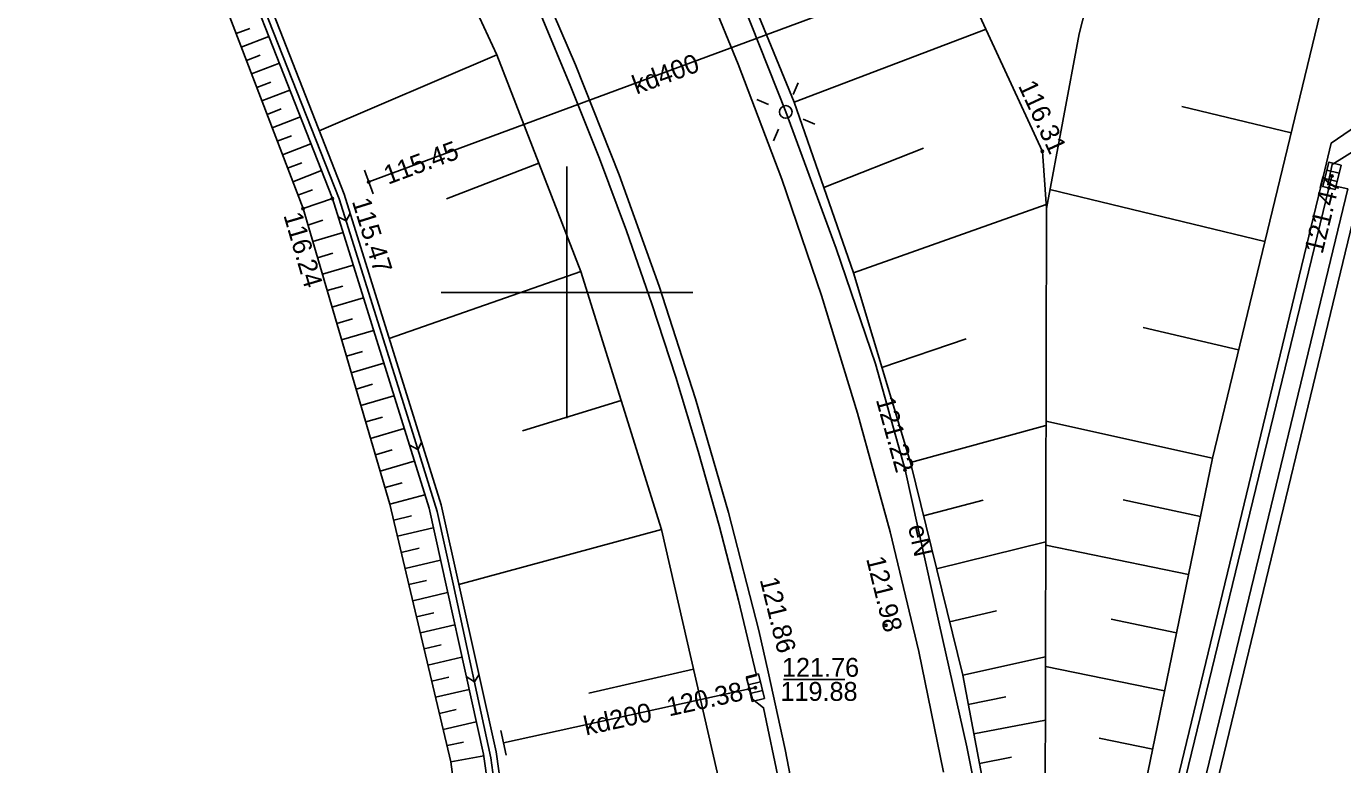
# Model space of a CAD drawing. Extents: x 6424617 to 6425697, y 5665845 to 5667190.
# Drawn here: x 6425378.5 to 6425430.8, y 5666881.2 to 5666910.6 of the extents above; entities that cross this region are included whole.
import ezdxf

# ---------------------------------------------------------------- set-up
doc = ezdxf.new("R2010")
doc.units = 0
for name, color, linetype in [('Warstwa 12', 7, 'Continuous'), ('Warstwa 13', 7, 'Continuous'), ('Warstwa 14', 7, 'Continuous'), ('Warstwa 15', 7, 'Continuous'), ('Warstwa 2', 7, 'Continuous'), ('Warstwa 20', 7, 'Continuous'), ('Warstwa 21', 7, 'Continuous'), ('Warstwa 25', 7, 'Continuous'), ('Warstwa 4', 7, 'Continuous'), ('Warstwa 47', 7, 'Continuous'), ('Warstwa 6', 7, 'Continuous'), ('Warstwa 63', 7, 'Continuous'), ('Warstwa 8', 7, 'Continuous'), ('Warstwa 9', 7, 'Continuous')]:
    doc.layers.add(name, color=color, linetype=linetype)

msp = doc.modelspace()

# ---------------------------------------------------------------- linework, layer by layer
at = {"layer": 'Warstwa 12'}
for points in [[(6425348.14, 5666997.42), (6425353.37, 5666990.86), (6425362.83, 5666978.49), (6425371.96, 5666966.45), (6425386.81, 5666946.74), (6425392.86, 5666938.27), (6425396.85, 5666931.85), (6425399.93, 5666926.36), (6425402.86, 5666920.8), (6425405.92, 5666914.19), (6425408.7, 5666907.17), (6425410.7, 5666901.75), (6425412.27, 5666897.16), (6425413.44, 5666892.95), (6425414.78, 5666886.9), (6425415.89, 5666881.95), (6425416.77, 5666877.58), (6425417.4, 5666873.25), (6425418.12, 5666868.16), (6425418.38, 5666863.9), (6425418.7, 5666858.55), (6425418.2, 5666857.76)], [(6425418.31, 5666914.08), (6425392.12, 5666904.39)], [(6425418.2, 5666857.76), (6425418.82, 5666858.12), (6425430.06, 5666904.59), (6425430.38, 5666905.93), (6425431.89, 5666906.96)], [(6425430.41, 5666904.63), (6425423.78, 5666877.4), (6425418.69, 5666856.25), (6425418.65, 5666856.01)], [(6425397.48, 5666882.11), (6425407.49, 5666884.3)]]:
    msp.add_lwpolyline(points, dxfattribs=at)
at = {"layer": 'Warstwa 14'}
msp.add_line((6425411.043, 5666884.619), (6425408.603, 5666884.619), dxfattribs=at)
for centre in [(6425392.12, 5666904.39), (6425430.41, 5666904.63), (6425430.292, 5666904.144), (6425413.44, 5666892.95), (6425407.49, 5666884.3), (6425407.246, 5666884.247)]:
    msp.add_circle(centre, 0.045, dxfattribs=at)
at = {"layer": 'Warstwa 2'}
msp.add_circle((6425408.7, 5666907.17), 0.25, dxfattribs=at)
at = {"layer": 'Warstwa 20'}
for points in [[(6425314.103, 5667029.211), (6425315.581, 5667026.396), (6425321.09, 5667017.329), (6425326.707, 5667009.007), (6425332.328, 5667001.644), (6425369.012, 5666954.157), (6425382.127, 5666936.484), (6425388.892, 5666925.984), (6425393.247, 5666917.98), (6425397.216, 5666909.432), (6425400.558, 5666900.834), (6425403.756, 5666890.579), (6425406.309, 5666879.499), (6425407.78, 5666870.067), (6425408.67, 5666859.825), (6425408.853, 5666850.565), (6425408.345, 5666840.039), (6425407.685, 5666833.993), (6425407.004, 5666828.248), (6425405.898, 5666821.141), (6425404.522, 5666813.522)], [(6425393.298, 5666813.657), (6425395.438, 5666825.508), (6425396.774, 5666840.178), (6425397.83, 5666855.444), (6425397.308, 5666867.017), (6425395.387, 5666881.357), (6425392.961, 5666891.594), (6425389.511, 5666903.33), (6425384.19, 5666917.231), (6425380.005, 5666924.769), (6425372.43, 5666937.379), (6425363.259, 5666950.219), (6425359.316, 5666956.212), (6425352.524, 5666966.198), (6425341.504, 5666981.912), (6425329.825, 5666997.688), (6425317.161, 5667014.853), (6425313.991, 5667019.921)], [(6425349.632, 5666996.03), (6425376.62, 5666961.102), (6425380.441, 5666956.131), (6425386.586, 5666947.957), (6425392.505, 5666939.498), (6425397.085, 5666932.217), (6425401.495, 5666924.286), (6425406.312, 5666914.18), (6425409.035, 5666907.556), (6425411.392, 5666900.784), (6425413.657, 5666893.241), (6425415.732, 5666884.803), (6425417.068, 5666877.78), (6425418.262, 5666868.956), (6425418.975, 5666860.884)], [(6425418.975, 5666860.884), (6425420.91, 5666870.31), (6425425.66, 5666893.41), (6425431.91, 5666919.26)]]:
    msp.add_lwpolyline(points, dxfattribs=at)
at = {"layer": 'Warstwa 21'}
for p, q in [((6425392.292, 5666903.921), (6425391.948, 5666904.859)), ((6425397.588, 5666881.622), (6425397.372, 5666882.598))]:
    msp.add_line(p, q, dxfattribs=at)
for points in [[(6425314.038, 5667023.847), (6425318.834, 5667016.073), (6425331.461, 5666998.529), (6425342.663, 5666983.502), (6425354.15, 5666967.599), (6425365.232, 5666951.474), (6425373.98, 5666938.422), (6425381.71, 5666925.538), (6425385.644, 5666917.945), (6425391.142, 5666903.901), (6425395.001, 5666891.557), (6425397.184, 5666881.754), (6425399.285, 5666866.812), (6425399.444, 5666855.685), (6425398.462, 5666840.068), (6425397.038, 5666824.899), (6425394.925, 5666813.637)], [(6425314.027, 5667022.896), (6425318.409, 5667015.8), (6425331.056, 5666998.236), (6425342.258, 5666983.209), (6425353.745, 5666967.307), (6425364.827, 5666951.201), (6425373.555, 5666938.149), (6425381.265, 5666925.286), (6425385.18, 5666917.733), (6425390.679, 5666903.729), (6425394.518, 5666891.426), (6425396.682, 5666881.663), (6425398.785, 5666866.781), (6425398.944, 5666855.694), (6425397.963, 5666840.107), (6425396.539, 5666824.968), (6425394.409, 5666813.644)], [(6425418.975, 5666860.884), (6425419.06, 5666903.33), (6425418.902, 5666905.6), (6425415.908, 5666912.076), (6425410.886, 5666921.5), (6425406.057, 5666930.53), (6425401.387, 5666938.317), (6425394.923, 5666946.546), (6425388.818, 5666954.159), (6425381.634, 5666961.791), (6425371.584, 5666973.036), (6425362.387, 5666983.346), (6425359.931, 5666986.941), (6425351.65, 5666994.223), (6425349.632, 5666996.03)], [(6425418.975, 5666860.884), (6425419.06, 5666903.33), (6425420.356, 5666910.275), (6425421.335, 5666914.059)]]:
    msp.add_lwpolyline(points, dxfattribs=at)
at = {"layer": 'Warstwa 25'}
for centre in [(6425418.902, 5666905.6), (6425390.679, 5666903.729), (6425389.511, 5666903.33), (6425412.68, 5666886.776), (6425408.792, 5666885.876)]:
    msp.add_circle(centre, 0.045, dxfattribs=at)
at = {"layer": 'Warstwa 4'}
for p, q in [((6425430.695, 5666904.74), (6425430.209, 5666904.86)), ((6425430.611, 5666904.4), (6425430.125, 5666904.52)), ((6425407.693, 5666884.528), (6425407.207, 5666884.413)), ((6425407.773, 5666884.187), (6425407.287, 5666884.072))]:
    msp.add_line(p, q, dxfattribs=at)
for points in [[(6425408.993, 5666907.86), (6425409.188, 5666908.321)], [(6425408.01, 5666907.463), (6425407.549, 5666907.658)], [(6425409.39, 5666906.877), (6425409.851, 5666906.682)], [(6425408.407, 5666906.48), (6425408.212, 5666906.019)]]:
    msp.add_lwpolyline(points, dxfattribs=at)
for points in [[(6425430.773, 5666905.055), (6425430.533, 5666904.085), (6425430.047, 5666904.205), (6425430.287, 5666905.175)], [(6425407.619, 5666884.844), (6425407.848, 5666883.871), (6425407.361, 5666883.756), (6425407.132, 5666884.729)]]:
    msp.add_lwpolyline(points, close=True, dxfattribs=at)
at = {"layer": 'Warstwa 47'}
for points in [[(6425314.103, 5667029.211), (6425315.581, 5667026.396), (6425321.09, 5667017.329), (6425326.707, 5667009.007), (6425332.328, 5667001.644), (6425369.012, 5666954.157), (6425382.127, 5666936.484), (6425388.892, 5666925.984), (6425393.247, 5666917.98), (6425397.216, 5666909.432), (6425400.558, 5666900.834), (6425403.756, 5666890.579), (6425406.309, 5666879.499), (6425407.78, 5666870.067), (6425408.67, 5666859.825), (6425408.853, 5666850.565), (6425408.345, 5666840.039), (6425407.685, 5666833.993), (6425407.004, 5666828.248), (6425405.898, 5666821.141), (6425404.522, 5666813.522)], [(6425434.482, 5666938.566), (6425431.91, 5666919.26), (6425425.66, 5666893.41), (6425420.91, 5666870.31), (6425418.975, 5666860.884)]]:
    msp.add_lwpolyline(points, dxfattribs=at)
at = {"layer": 'Warstwa 6'}
for points in [[(6425436.9, 5666928.04), (6425436.812, 5666928.004), (6425436.564, 5666927.008), (6425436.159, 5666926.755), (6425435.965, 5666925.969), (6425436.293, 5666925.883), (6425431.397, 5666905.695), (6425430.416, 5666905.082), (6425430.241, 5666904.285), (6425431.039, 5666904.111), (6425424.834, 5666878.494), (6425423.823, 5666877.862), (6425423.658, 5666877.065), (6425424.455, 5666876.9), (6425419.634, 5666856.991), (6425418.663, 5666856.398), (6425418.469, 5666855.612), (6425419.071, 5666854.62), (6425418.186, 5666851.005), (6425418.674, 5666850.886)], [(6425408.433, 5666880.528), (6425407.819, 5666883.503), (6425407.375, 5666883.841), (6425407.14, 5666884.676), (6425407.532, 5666884.789), (6425406.822, 5666887.774), (6425406.051, 5666890.743), (6425405.219, 5666893.697), (6425404.327, 5666896.632), (6425403.374, 5666899.549), (6425402.362, 5666902.445), (6425401.291, 5666905.321), (6425400.161, 5666908.173), (6425398.973, 5666911.002)]]:
    msp.add_lwpolyline(points, dxfattribs=at)
at = {"layer": 'Warstwa 63'}
for p, q in [((6425400, 5666905), (6425400, 5666895)), ((6425405, 5666900), (6425395, 5666900))]:
    msp.add_line(p, q, dxfattribs=at)
at = {"layer": 'Warstwa 8'}
for p, q in [((6425418.674, 5666850.886), (6425437.29, 5666927.885)), ((6425398.479, 5666913.352), (6425400.344, 5666909.037)), ((6425404.938, 5666913.593), (6425406.811, 5666909.069)), ((6425400.344, 5666909.037), (6425402.073, 5666904.666)), ((6425406.811, 5666909.069), (6425408.538, 5666904.496)), ((6425402.073, 5666904.666), (6425403.664, 5666900.244)), ((6425408.538, 5666904.496), (6425410.12, 5666899.872)), ((6425403.664, 5666900.244), (6425405.117, 5666895.774)), ((6425410.12, 5666899.872), (6425411.556, 5666895.2)), ((6425405.117, 5666895.774), (6425406.429, 5666891.261)), ((6425411.556, 5666895.2), (6425412.845, 5666890.485)), ((6425406.429, 5666891.261), (6425407.631, 5666886.573)), ((6425412.845, 5666890.485), (6425413.985, 5666885.732)), ((6425407.631, 5666886.573), (6425407.998, 5666884.923)), ((6425413.985, 5666885.732), (6425414.975, 5666880.946)), ((6425407.998, 5666884.923), (6425408.681, 5666881.849)), ((6425408.681, 5666881.849), (6425409.578, 5666877.094))]:
    msp.add_line(p, q, dxfattribs=at)
at = {"layer": 'Warstwa 9'}
for p, q in [((6425387.348, 5666912.851), (6425390.945, 5666903.719)), ((6425386.85, 5666910.28), (6425387.396, 5666910.49)), ((6425387.055, 5666909.746), (6425388.151, 5666910.166)), ((6425409.035, 5666907.556), (6425416.659, 5666910.451)), ((6425387.26, 5666909.212), (6425387.81, 5666909.422)), ((6425387.464, 5666908.677), (6425388.57, 5666909.101)), ((6425397.216, 5666909.432), (6425390.155, 5666906.423)), ((6425387.669, 5666908.142), (6425388.224, 5666908.355)), ((6425387.874, 5666907.607), (6425388.988, 5666908.034)), ((6425428.785, 5666906.335), (6425424.444, 5666907.385)), ((6425388.078, 5666907.072), (6425388.638, 5666907.287)), ((6425388.283, 5666906.538), (6425389.407, 5666906.969)), ((6425388.488, 5666906.004), (6425389.052, 5666906.22)), ((6425388.692, 5666905.469), (6425389.825, 5666905.903)), ((6425410.214, 5666904.17), (6425414.178, 5666905.727)), ((6425388.897, 5666904.934), (6425389.466, 5666905.152)), ((6425389.102, 5666904.399), (6425390.244, 5666904.837)), ((6425398.887, 5666905.133), (6425395.216, 5666903.714)), ((6425389.306, 5666903.864), (6425389.884, 5666904.073)), ((6425389.511, 5666903.33), (6425390.68, 5666903.725)), ((6425390.945, 5666903.719), (6425393.878, 5666894.415)), ((6425427.743, 5666902.027), (6425419.202, 5666904.092)), ((6425411.392, 5666900.784), (6425419.048, 5666903.499)), ((6425389.703, 5666902.678), (6425390.296, 5666902.865)), ((6425390.906, 5666903.003), (6425391.223, 5666902.838)), ((6425391.38, 5666903.14), (6425391.223, 5666902.838)), ((6425389.894, 5666902.026), (6425391.1, 5666902.381)), ((6425390.086, 5666901.374), (6425390.694, 5666901.553)), ((6425390.278, 5666900.722), (6425391.505, 5666901.083)), ((6425400.558, 5666900.834), (6425392.934, 5666898.169)), ((6425390.47, 5666900.07), (6425391.088, 5666900.252)), ((6425390.661, 5666899.418), (6425391.91, 5666899.785)), ((6425390.852, 5666898.766), (6425391.482, 5666898.951)), ((6425391.044, 5666898.114), (6425392.314, 5666898.488)), ((6425426.702, 5666897.718), (6425422.912, 5666898.604)), ((6425412.524, 5666897.012), (6425415.865, 5666898.161)), ((6425391.236, 5666897.462), (6425391.876, 5666897.65)), ((6425391.428, 5666896.81), (6425392.72, 5666897.19)), ((6425391.62, 5666896.158), (6425392.271, 5666896.35)), ((6425391.811, 5666895.506), (6425393.124, 5666895.892)), ((6425402.157, 5666895.706), (6425398.238, 5666894.496)), ((6425392.002, 5666894.854), (6425392.664, 5666895.049)), ((6425425.66, 5666893.41), (6425419.043, 5666894.888)), ((6425392.194, 5666894.202), (6425393.529, 5666894.595)), ((6425393.878, 5666894.415), (6425394.836, 5666891.302)), ((6425413.657, 5666893.241), (6425419.043, 5666894.708)), ((6425393.731, 5666893.949), (6425394.077, 5666893.766)), ((6425394.224, 5666894.043), (6425394.077, 5666893.766)), ((6425392.386, 5666893.55), (6425393.059, 5666893.748)), ((6425392.578, 5666892.898), (6425393.934, 5666893.297)), ((6425392.77, 5666892.246), (6425393.456, 5666892.438)), ((6425392.961, 5666891.594), (6425394.351, 5666891.962)), ((6425414.176, 5666891.132), (6425416.55, 5666891.75)), ((6425425.185, 5666891.1), (6425422.112, 5666891.762)), ((6425394.836, 5666891.302), (6425395.481, 5666888.426)), ((6425393.113, 5666890.954), (6425393.816, 5666891.13)), ((6425393.264, 5666890.314), (6425394.689, 5666890.652)), ((6425403.756, 5666890.579), (6425395.703, 5666888.403)), ((6425393.416, 5666889.674), (6425394.124, 5666889.842)), ((6425414.694, 5666889.022), (6425419.033, 5666890.089)), ((6425424.71, 5666888.79), (6425419.033, 5666889.958)), ((6425393.568, 5666889.035), (6425394.974, 5666889.369)), ((6425393.72, 5666888.395), (6425394.418, 5666888.561)), ((6425393.871, 5666887.755), (6425395.259, 5666888.084)), ((6425395.481, 5666888.426), (6425396.973, 5666881.514)), ((6425394.023, 5666887.115), (6425394.712, 5666887.279)), ((6425415.213, 5666886.912), (6425417.072, 5666887.347)), ((6425424.235, 5666886.48), (6425421.632, 5666887.016)), ((6425394.174, 5666886.476), (6425395.543, 5666886.801)), ((6425394.326, 5666885.836), (6425395.006, 5666885.998)), ((6425394.477, 5666885.196), (6425395.828, 5666885.517)), ((6425415.732, 5666884.803), (6425419.024, 5666885.52)), ((6425405.033, 5666885.039), (6425400.876, 5666884.081)), ((6425423.76, 5666884.17), (6425419.024, 5666885.145)), ((6425394.628, 5666884.556), (6425395.3, 5666884.715)), ((6425396, 5666884.738), (6425396.322, 5666884.53)), ((6425396.503, 5666884.811), (6425396.322, 5666884.53)), ((6425394.78, 5666883.916), (6425396.113, 5666884.232)), ((6425415.954, 5666883.632), (6425417.446, 5666883.938)), ((6425394.932, 5666883.276), (6425395.593, 5666883.433)), ((6425395.084, 5666882.637), (6425396.397, 5666882.949)), ((6425416.177, 5666882.462), (6425419.019, 5666883.003)), ((6425423.285, 5666881.86), (6425421.152, 5666882.299)), ((6425395.236, 5666881.997), (6425395.89, 5666882.135)), ((6425395.387, 5666881.357), (6425396.691, 5666881.598)), ((6425396.973, 5666881.514), (6425398.984, 5666866.811)), ((6425416.4, 5666881.292), (6425417.67, 5666881.534))]:
    msp.add_line(p, q, dxfattribs=at)
for points in [[(6425421.335, 5666914.059), (6425420.356, 5666910.275), (6425419.06, 5666903.33), (6425418.975, 5666860.884), (6425420.91, 5666870.31), (6425425.66, 5666893.41), (6425431.91, 5666919.26)], [(6425394.925, 5666813.637), (6425397.038, 5666824.899), (6425398.462, 5666840.068), (6425399.444, 5666855.685), (6425399.285, 5666866.812), (6425397.184, 5666881.754), (6425395.001, 5666891.557), (6425391.142, 5666903.901), (6425385.644, 5666917.945)], [(6425385.644, 5666917.945), (6425391.142, 5666903.901), (6425395.001, 5666891.557), (6425397.184, 5666881.754), (6425399.285, 5666866.812), (6425399.444, 5666855.685), (6425398.462, 5666840.068), (6425397.038, 5666824.899), (6425394.925, 5666813.637)], [(6425404.522, 5666813.522), (6425405.898, 5666821.141), (6425407.004, 5666828.248), (6425407.685, 5666833.993), (6425408.345, 5666840.039), (6425408.853, 5666850.565), (6425408.67, 5666859.825), (6425407.78, 5666870.067), (6425406.309, 5666879.499), (6425403.756, 5666890.579), (6425400.558, 5666900.834), (6425397.216, 5666909.432), (6425393.247, 5666917.98)], [(6425385.18, 5666917.733), (6425390.679, 5666903.729), (6425394.518, 5666891.426), (6425396.682, 5666881.663), (6425398.785, 5666866.781), (6425398.944, 5666855.694), (6425397.963, 5666840.107), (6425396.539, 5666824.968), (6425394.409, 5666813.644)], [(6425385.18, 5666917.733), (6425390.679, 5666903.729), (6425394.518, 5666891.426), (6425396.682, 5666881.663), (6425398.785, 5666866.781), (6425398.944, 5666855.694), (6425397.963, 5666840.107), (6425396.539, 5666824.968), (6425394.409, 5666813.644)], [(6425393.298, 5666813.657), (6425395.438, 5666825.508), (6425396.774, 5666840.178), (6425397.83, 5666855.444), (6425397.308, 5666867.017), (6425395.387, 5666881.357), (6425392.961, 5666891.594), (6425389.511, 5666903.33), (6425384.19, 5666917.231)], [(6425406.312, 5666914.18), (6425409.035, 5666907.556), (6425411.392, 5666900.784), (6425413.657, 5666893.241), (6425415.732, 5666884.803), (6425417.068, 5666877.78), (6425418.262, 5666868.956), (6425418.975, 5666860.884), (6425419.06, 5666903.33), (6425418.902, 5666905.6), (6425415.908, 5666912.076)]]:
    msp.add_lwpolyline(points, dxfattribs=at)

# ---------------------------------------------------------------- texts
at = {"layer": 'Warstwa 13'}
for s, rotation, p in [('kd400', 20.3056, (6425402.766, 5666907.855)), ('eN', 282.4911, (6425413.554, 5666890.7)), ('kd200', 12.3415, (6425400.758, 5666882.397))]:
    msp.add_text(s, height=0.75, rotation=rotation, dxfattribs=at).set_placement(p)
at = {"layer": 'Warstwa 14'}
for s, rotation, p in [('115.45', 20.3056, (6425392.891, 5666904.275)), ('121.47', 76.318, (6425430.033, 5666901.496)), ('121.22', 285.5335, (6425412.274, 5666895.743)), ('120.38', 12.3415, (6425404.06, 5666883.156))]:
    msp.add_text(s, height=0.75, rotation=rotation, dxfattribs=at).set_placement(p)
msp.add_text('119.88', height=0.75, dxfattribs=at).set_placement((6425408.486, 5666883.776))
at = {"layer": 'Warstwa 15'}
msp.add_text('121.76', height=0.75, dxfattribs=at).set_placement((6425408.548, 5666884.732))
at = {"layer": 'Warstwa 25'}
for s, rotation, p in [('116.31', 294.8097, (6425417.922, 5666908.212)), ('115.47', 287.3613, (6425391.445, 5666903.624)), ('116.24', 286.3815, (6425388.725, 5666903.067)), ('121.98', 283.8146, (6425411.89, 5666889.425)), ('121.86', 283.8146, (6425407.661, 5666888.594))]:
    msp.add_text(s, height=0.75, rotation=rotation, dxfattribs=at).set_placement(p)

doc.saveas('drawing.dxf')
